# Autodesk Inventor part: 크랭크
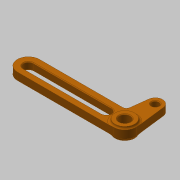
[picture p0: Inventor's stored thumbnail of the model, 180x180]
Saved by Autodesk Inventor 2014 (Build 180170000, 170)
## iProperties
Created: 2019-09
Part Number: 크랭크
Material: 알루미늄 6061
Document SubType Name: Modeling
Designer: mduedu
Density: 2.71 g/cm^3
Appearance: 주황색
Mass: 23.0159 g
Surface Area: 54.7149 cm^2
Volume: 8.49295 cm^3
Author: mduedu
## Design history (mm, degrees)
sketch "스케치1"
  geometry: L1 (0, 0)-(79, 0); L2 (0, 9)-(79, 9); L3 (10.637, -9)-(79, -9); L4 (0, 0)-(0, -25); L5 (-8.935, -1.08)-(-5.957, -25.72); L6 (7.659, -11.64)-(5.957, -25.72); L7 (79, -4)-(15, -4); L8 (15, 4)-(79, 4); C1 r 3 at (0, -25); A1 r 9 centre (0, 0) between (0, 9) and (-8.935, -1.08); A2 r 9 centre (79, 0) between (79, -9) and (79, 9); A3 r 6 centre (0, -25) between (-5.957, -25.72) and (5.957, -25.72); A4 r 3 centre (10.637, -12) between (10.637, -9) and (7.659, -11.64); A5 r 4 centre (79, 0) between (79, -4) and (79, 4); A6 r 4 centre (15, 0) between (15, -4) and (15, 4); 1 further point
  constraints: 16 end point, 13 point on circle, 12 tangent, 7 centre point, 5 coincident, 3 horizontal, 2 point on line, 1 equal radius, 1 perpendicular, 1 other
  dimensions: "d0" = 79 distance of L1.start L1.end; "d2" = 25 distance of L1.start L4.end; "d3" = 3 radius of A4; "d4" = 9 radius of A1; "d5" = 6 radius of A3; "d6" = 8 diameter of A5; "d7" = 64 distance of A6.centre L1.end; "d8" = 6 diameter of C1
extrude "돌출1" new body sketch "스케치1" stored distance "d9" = 6; taper "d10" = 0 deg
sketch "스케치2"
  geometry: C1 r 8 at (0, 0); 1 further point
  constraints: 1 centre point, 1 coincident
  dimensions: "d11" = 16 diameter of C1
extrude "돌출2" join sketch "스케치2" stored distance "d12" = 10; taper "d13" = 0 deg
sketch "스케치3"
  geometry: C1 r 4.5 at (0, 0); 1 further point
  constraints: 1 centre point, 1 coincident
  dimensions: "d14" = 9 diameter of C1
extrude "돌출3" cut sketch "스케치3" stored distance "d15" = 10; taper "d16" = 0 deg
fillet "모깎기1" dims "d17" = 2
chamfer "모따기1" distance "d18" = 0.5; stored, may be unused: second distance "d19" = 2, angle "d20" = 45 deg
node "솔리드1"
